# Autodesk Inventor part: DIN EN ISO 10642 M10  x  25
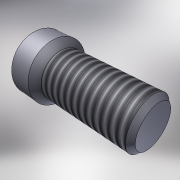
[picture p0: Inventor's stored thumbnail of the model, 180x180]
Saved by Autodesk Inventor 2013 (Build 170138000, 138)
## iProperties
Created: 2012-02
Part Number: DIN EN ISO 10642 M10  x  25
Material: Generic
Document SubType Name: Modeling
Designer: tedescj
Density: 1 g/cm^3
Mass: 2.10791 g
Surface Area: 11.3576 cm^2
Volume: 2.10791 cm^3
Translation Standard: STEP AP214IS
FileName: D:\_Workspace\Dropbox\Launch 2013, Inprocess\Front Loader, CIS\_Data\M10-6gx25.58.019.stp
PreProcessor: Autodesk Inventor 2012
PostProcessor: Build: 190, Release: 2012 SP1 - Date: Mon 08/08/2011
Sent Units: millimeter
Uncertainty: 0.01
Author: tedescj
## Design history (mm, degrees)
feature "Base1"
thread "Thread1" dims "d0" = 12, "d1" = 0
body "Solid1"
